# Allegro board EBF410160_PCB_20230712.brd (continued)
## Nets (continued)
CTP0_RST: J6.61 J21.12 R166.2
CTP1_INT: J7.55 J22.11 R164.2
CTP1_RST: J7.57 J22.12 R168.2
DBG_RX: R40.2 U10.2(A)
DBG_RXD: D6.2 J9.3 R40.1
DBG_TX: R39.2 U9.4(Y)
DBG_TXD: D5.2 J9.2 R39.1
DM4: D38.2 J27.36(USB-D-) R210.1
DP4: D39.2 J27.38(USB-D+) R211.1
DSI0_RST: J5.60 J21.15
DSI0_TE: J5.58 R160.1
DSI1_RST: J7.53 J22.15
DSI1_TE: J7.51 R161.1
EDP_AUXN: C146.2 J25.10 R191.2
EDP_AUXP: C147.2 J25.9 R188.2
EDP_BL_EN: J4.39 J25.22
EDP_BL_PWM: J5.5 J25.23
EDP_HPDIN_M0: J6.66 J25.17
EDP_PWR_EN: J6.76 R192.1 R196.1
EDP_TP_INT: J7.65 J26.2 R189.2
EDP_TP_RESET: J6.57 J26.3 R190.2
EDP_TX_AUXN: C146.1 J6.62
EDP_TX_AUXP: C147.1 J6.60
EDP_TX_D0N: J6.44 J25.6
EDP_TX_D0P: J6.42 J25.7
EDP_TX_D1N: J6.48 J25.3
EDP_TX_D1P: J6.46 J25.4
EXT_PWR_EN: J4.27 R1.1 R3.1 R19.1 R24.1
FAN: C30.1 Q1.2(SOURCE) R9.2 R10.2 R12.1
FSPI_CLK: J6.29 U8.6(CLK)
FSPI_CS0N: J6.31 U8.1(C\S\)
FSPI_D0: J6.33 J8.2 U8.5(DI/IO0)
FSPI_D1: J6.35 U8.2(DO/IO1)
FSPI_D2: J6.37 R36.2 U8.3(W\P\/IO2)
FSPI_D3: J6.39 R37.2 U8.7(HOLD/IO3)
GMAC1_INT: J5.10 R111.1
GMAC1_MCLKINOUT_M1: J7.56 R112.1 R113.1
GMAC1_MDC_M1: J7.62 R108.2 U16.13(MDC)
GMAC1_MDIO_M1: J7.60 R109.2 U16.14(MDIO)
GMAC1_RSTN: C84.1 D28.1 J5.4
GMAC1_RXCLK_M1: J7.36 R95.2 R101.1
GMAC1_RXD0_M1: J7.34 R93.2 R96.1
GMAC1_RXD1_M1: J7.32 R94.2 R97.1
GMAC1_RXD2_M1: J7.30 R99.1 R103.1
GMAC1_RXD3_M1: J7.28 R100.1 R104.1
GMAC1_RXDV_CRS_M1: J7.38 R102.1 R105.1
GMAC1_TXCLK_M1: J7.44 U16.20(TXC)
GMAC1_TXD0_M1: J7.52 U16.18(TXD0)
GMAC1_TXD1_M1: J7.50 U16.17(TXD1)
GMAC1_TXD2_M1: J7.48 U16.16(TXD2)
GMAC1_TXD3_M1: J7.46 U16.15(TXD3)
GMAC1_TXEN_M1: J7.42 U16.19(TXCTL)
GPIO2_B7: J7.47 R48.2
GPIO2_C0: J7.49 R49.2
HDMI_5V: C129.1 D32.1 D37.2 Q9.1(GATE) Q10.1(GATE) R157.1 R159.1 U25.18
HDMI_TX0N_PORT: J5.48 U25.9 U27.4(D2+) U27.7(NC3)
HDMI_TX0P_PORT: J5.46 U25.7 U27.5(D2-) U27.6(NC4)
HDMI_TX1N_PORT: J5.44 U25.6 U26.1(D1+) U26.10(NC1)
HDMI_TX1P_PORT: J5.42 U25.4 U26.2(D1-) U26.9(NC2)
HDMI_TX2N_PORT: J5.40 U25.3 U26.4(D2+) U26.7(NC3)
HDMI_TX2P_PORT: J5.38 U25.1 U26.5(D2-) U26.6(NC4)
HDMI_TX_CEC_PORT: D36.2 Q8.3(DRAIN) U25.13
HDMI_TX_HPD_PORT: D33.2 R153.2 R154.1 U25.19
HDMI_TX_HPDIN: J5.34 R153.1
HDMI_TXCLKN_PORT: J5.50 U25.12 U27.1(D1+) U27.10(NC1)
HDMI_TXCLKP_PORT: J5.52 U25.10 U27.2(D1-) U27.9(NC2)
HDMI_TXDDC_SCL_PORT: D35.2 Q9.3(DRAIN) R157.2 U25.15
HDMI_TXDDC_SDA_PORT: D34.2 Q10.3(DRAIN) R159.2 U25.16
HDMITX_CEC_M0: J5.32 Q8.2(SOURCE) R155.2
HDMITX_SCL: J5.30 Q9.2(SOURCE) R156.2
HDMITX_SDA: J5.28 Q10.2(SOURCE) R158.2
HOST1_DM: J18.2(D-) R136.1 U19.4(D2+) U19.7(NC3)
HOST1_DP: J18.3(D+) R137.1 U19.5(D2-) U19.6(NC4)
HP_DET: C173.1 J6.80 R215.1
HP_SNS: J4.36 J28.1 J29.1 R216.1 R218.1
HPL_OUT: C175.1 J4.34
HPR_OUT: C176.1 J4.38
HUB_3V3: C126.1 C127.1 C128.1 R144.1 R145.1 R151.2 U22.1(OVCUR#) U22.20(VDD3V3)
HUB_DM1: R129.2 U22.11(DM1)
HUB_DM2: R138.2 U22.9(DM2)
HUB_DM3: R131.2 U22.7(DM3)
HUB_DM4: R210.2 U22.5(DM4)
HUB_DP1: R130.2 U22.12(DP1)
HUB_DP2: R139.2 U22.10(DP2)
HUB_DP3: R132.2 U22.8(DP3)
HUB_DP4: R211.2 U22.6(DP4)
I2C0_SCL_PMIC: J6.3 U12.6(SCL)
I2C0_SDA_PMIC: J6.5 U12.5(SDA)
I2C1_SCL: J6.7 J21.9 J23.6 R163.2
I2C1_SDA: J6.9 J21.10 J23.5 R167.2
I2C2_SCL_M1: J6.51 R222.2
I2C2_SDA_M1: J6.53 R221.2
I2C3_SCL_M0: J6.72 R219.2
I2C3_SDA_M0: J6.70 R220.2
I2C4_SCL_M0: J7.29 J26.4
I2C4_SDA_M0: J7.31 J26.5
I2C5_SCL_M0: J7.25 J22.9 J24.6 R165.2
I2C5_SDA_M0: J7.27 J22.10 J24.5 R169.2
LCD0_BL_PWM: J5.9 J21.13
LCD1_BL_PWM: J5.11 J22.13
MDIN0_PHY: J17.3(TD1-) U16.2(MDIN0)
MDIN1_PHY: J17.7(RD1-) U16.5(MDIN1)
MDIN2_PHY: J17.6(TD2-) U16.7(MDIN2)
MDIN3_PHY: J17.9(RD2-) U16.10(MDIN3)
MDIP0_PHY: J17.2(TD1+) U16.1(MDIP0)
MDIP1_PHY: J17.4(RD1+) U16.4(MDIP1)
MDIP2_PHY: J17.5(TD2+) U16.6(MDIP2)
MDIP3_PHY: J17.8(RD2+) U16.9(MDIP3)
MIC_INN: C174.2 D44.2 J4.30 J30.1 R217.1
MIC_INP: C174.1 D41.2 J4.28 J29.2 J29.3 J29.4 J29.5 J30.2 R213.2
MINIPCIE_3V3: C155.1 C159.1 C160.1 C161.1 C167.1 C168.1 C169.1 C170.1 J27.2(VBAT1) J27.24(VBAT5) J27.39(VBAT2) J27.41(VBAT3) J27.52(VBAT4) L10.2 R201.1 R205.1
MINIPCIE_NWDISABLE: J7.61 R208.2
MIPI0_PWR_EN: J6.74 R171.1
MIPI1_PWR_EN: J5.16 R170.1
MIPI_CSI_RX_CLK0N: J5.78 J23.10
MIPI_CSI_RX_CLK0P: J5.76 J23.9
MIPI_CSI_RX_CLK1N: J5.77 J24.10
MIPI_CSI_RX_CLK1P: J5.75 J24.9
MIPI_CSI_RX_D0N: J5.70 J23.12
MIPI_CSI_RX_D0P: J5.68 J23.11
MIPI_CSI_RX_D1N: J5.74 J23.8
MIPI_CSI_RX_D1P: J5.72 J23.7
MIPI_CSI_RX_D2N: J5.69 R178.1 R180.1
MIPI_CSI_RX_D2P: J5.67 R176.1 R177.1
MIPI_CSI_RX_D3N: J5.73 R184.1 R185.1
MIPI_CSI_RX_D3P: J5.71 R182.1 R183.1
MIPI_DSI_TX0_CLKN: J5.53 J21.24
MIPI_DSI_TX0_CLKP: J5.51 J21.23
MIPI_DSI_TX0_D0N: J5.43 J21.27
MIPI_DSI_TX0_D0P: J5.41 J21.26
MIPI_DSI_TX0_D1N: J5.47 J21.21
MIPI_DSI_TX0_D1P: J5.45 J21.20
MIPI_DSI_TX0_D2N: J5.59 J21.18
MIPI_DSI_TX0_D2P: J5.57 J21.17
MIPI_DSI_TX0_D3N: J5.63 J21.30
MIPI_DSI_TX0_D3P: J5.61 J21.29
MIPI_DSI_TX1_CLKN: J5.27 J22.24
MIPI_DSI_TX1_CLKP: J5.25 J22.23
MIPI_DSI_TX1_D0N: J5.17 J22.27
MIPI_DSI_TX1_D0P: J5.15 J22.26
MIPI_DSI_TX1_D1N: J5.21 J22.21
MIPI_DSI_TX1_D1P: J5.19 J22.20
MIPI_DSI_TX1_D2N: J5.33 J22.18
MIPI_DSI_TX1_D2P: J5.31 J22.17
MIPI_DSI_TX1_D3N: J5.37 J22.30
MIPI_DSI_TX1_D3P: J5.35 J22.29
OTG0_DM: D30.2 J19.A7(DN1) J19.B7(DN2) R133.1
OTG0_DP: D31.2 J19.A6(DP1) J19.B6(DP2) R134.1
PCIE20_CLKREQN_M0: J7.37 R207.1
PCIE20_PERSTN_M0: J7.59 R209.2
PCIE20_REFCLKN: J4.54 J27.11(VDD-EXT)
PCIE20_REFCLKP: J4.52 J27.13(RESERVED)
PCIE20_RXN: J4.48 J27.23(UART-RXD)
PCIE20_RXP: J4.46 J27.25(UART-RTS)
PCIE20_TXN: C165.1 J4.44
PCIE20_TXP: C166.1 J4.42
PCIE20_WAKEN_M0: J7.39 R206.1
PCIE_PWR_EN: J4.43 R204.1
PE_TXN: C165.2 J27.31(UART-TXD)
PE_TXP: C166.2 J27.33(PERST2)
PHY1_LED1: J17.14(YELA) R116.1 U16.33(LED1)
PHY1_LED2: J17.11(GRLA) R117.1 U16.34(LED2)
PHY_CLKOUT125: R112.2 U16.35(CLKOUT)
PWM2_M0: J5.8 R17.1
PWM3_IR: C62.1 J5.7 R46.1
PWR_3V3_EN: J6.59 R30.1
PWR_5V_EN: J4.35 R32.1
PWR_12V_EN: J4.41 R28.1
PWRON_KEY: C56.1 D3.2 J4.25 SW1.3(B1) SW1.4(B2)
RECOVERY: J6.16 R41.2
RESET_KEY: C58.1 D4.2 J4.29 SW2.3(B1) SW2.4(B2)
RS485_1_A: D26.2 J13.1 R71.2 R80.1 U14.6(A)
RS485_1_B: D24.2 R73.1 R76.1 R79.1 U14.7(B)
RS485_2_A: D27.2 J14.1 R72.2 R82.1 U15.6(A)
RS485_2_B: D25.2 R74.1 R78.1 R81.1 U15.7(B)
RX8010_NIRQ1: J5.64 U12.7(/IRQ1)
RX8010_NIRQ2: J5.62 U12.3(/IRQ2)
RXD1_232: D12.2 R58.1 U13.13(R1IN)
RXD2_232: D11.2 R56.1 U13.8(R2IN)
SARADC_VIN1: J6.18 R43.2
SDMMC0_CLK: J6.13 R63.1
SDMMC0_CMD: J6.15 R62.1
SDMMC0_D0: J6.19 R64.1
SDMMC0_D1: J6.21 R65.1
SDMMC0_D2: J6.23 R60.1
SDMMC0_D3: J6.25 R61.1
SDMMC0_DET: J6.17 R66.1
SIM_CLK0: J27.12(USIM-CLK) R200.1
SIM_DATA0: J27.10(USIM-DATA) R202.1
SIM_RST0: J27.14(USIM-RST) R199.1
SIM_VDD: J27.8(USIM-VDD) R198.1 U36.1(VCC) U37.1
SPKN_OUT: D46.2 J4.24 J31.2
SPKP_OUT: D45.2 J4.22 J31.1
SS_TXN: C112.1 J18.8(TX-) U19.2(D1-) U19.9(NC2)
SS_TXP: C113.1 J18.9(TX+) U19.1(D1+) U19.10(NC1)
TXD1_232: D14.2 R59.1 U13.14(T1OUT)
TXD2_232: D13.2 R57.1 U13.7(T2OUT)
UART1_DIR: J7.43 R75.1 U14.2(R\E\) U14.3(DE)
UART1_RX_M0: J7.10 R69.2 U14.1(RXD)
UART1_TX_M0: J7.8 R67.2 U14.4(TXD)
UART2_RX_M0_DEBUG: J5.22 R42.2 U10.4(Y)
UART2_TX_M0_DEBUG: J5.20 R38.2 U9.2(A)
UART3_RX_M1: J7.5 R52.2 U13.9(R2OUT)
UART3_TX_M1: J7.3 R53.2 U13.10(T2IN)
UART4_RX_M1: J7.9 R54.2 U13.12(R1OUT)
UART4_TX_M1: J7.7 R55.2 U13.11(T1IN)
UART6_DIR: J7.45 R77.1 U15.2(R\E\) U15.3(DE)
UART6_RX_M0: J7.13 R70.2 U15.1(RXD)
UART6_TX_M0: J7.11 R68.2 U15.4(TXD)
UART7_RX_M0: J7.17 R223.2
UART7_TX_M0: J7.15 R224.2
UART9_RX_M1: J7.21 R225.2
UART9_TX_M1: J7.19 R226.2
USB2_HOST2_DM: J7.74 R126.1
USB2_HOST2_DP: J7.72 R125.1
USB2_HOST3_DM: J7.68 R142.2
USB2_HOST3_DP: J7.66 R141.2
USB3_HOST1_DM: J4.80 R136.2
USB3_HOST1_DP: J4.78 R137.2
USB3_HOST1_SSRXN: J4.60 J18.5(RX-) U18.2(D1-) U18.9(NC2)
USB3_HOST1_SSRXP: J4.58 J18.6(RX+) U18.1(D1+) U18.10(NC1)
USB3_HOST1_SSTXN: C112.2 J4.64
USB3_HOST1_SSTXP: C113.2 J4.62
USB20_HOST_PWR_EN: J7.67 R140.1
USB20_OTG_PWR_EN: J4.37 R149.1
USB30_HOST_PWR_EN: J5.14 R146.1
USB OTG: C123.1 C124.1 J19.A4(VBUS1) J19.A9(VBUS2) J19.B4(VBUS4) J19.B9(VBUS3) R148.1 U24.1(OUT)
USB_OTG0_DM: J6.6 R133.2
USB_OTG0_DP: J6.4 R134.2
USB_OTG0_ID: J6.10 R135.2
USB_OTG0_VBUSDET: J6.12 R148.2 R150.1
USER_LED: J5.6 R45.2
WLAN_PWR_EN: J4.45 R128.1
N02088: F1.1 J1.4
N03633: C7.1 U3.6(BOOT)
N03641: C7.2 L1.1 U3.2(SW)
N03801: C8.2 R4.2 R6.1 U3.4(FB)
N28501: C28.1 U5.6(BOOT)
N28533: C28.2 L3.1 U5.2(SW)
N15118698: C4.1 R1.2 U1.4(EN)
N15119063: R2.1 U1.3(ISET)
N15122947: C9.1 R3.2 U2.4(EN)
N15123057: R5.1 U2.3(ISET)
N15599533: R96.2 U16.25(RXD0)
N15599537: R97.2 U16.24(RXD1)
N15599541: R99.2 U16.23(RXD2)
N15599545: R100.2 U16.22(RXD3)
N15599549: R101.2 U16.27(RXC)
N15599553: R102.2 U16.26(RXCTL)
N15599792: R90.2 R91.1 R93.1 R94.1 R95.1
N15600759: R106.2 R107.1 R108.1 R109.1
N15600826: R110.2 R111.2 U16.31(INTB)
N15601838: C81.1 U16.37(XTAL_OUT) Y1.1
N15601846: C82.1 U16.36(XTAL_IN) Y1.3
N15602173: D28.2 R119.2 R120.2 U16.12(PHYRSTB)
N15602572: R118.1 U16.32(LED0)
N15602600: R117.2 R121.2 R122.1
N15603170: C83.1 J17.1(CT)
N15605512: R98.1 U16.39(RSET)
N15605755: C77.1 C78.1 R89.1 R92.1 U16.28(DVDD_RG)
N15611443: C116.1 R140.2 U21.4(EN)
N15611553: R143.1 U21.3(ISET)
N15653247: C122.1 R149.2 U24.4(EN)
N15653357: R152.1 U24.3(ISET)
N15653957: C119.1 R146.2 U23.4(EN)
N15654067: R147.1 U23.3(ISET)
N15659726: C18.2 R7.2 R8.1 U3.5(EN)
N15752445: L9.1 U25.G1(20) U25.G2(21) U25.G3(22) U25.G4(23)
N15772454: J22.14 R161.2
N15774097: J21.14 R160.2
N15830872: C176.2 D43.2 J28.3 J28.5
N15830941: C175.2 D42.2 J28.2 R215.2
N15838979: J28.4 R214.2
N15851038: C171.1 R212.2 R213.1
N15980269: J13.2 R73.2
N16735828: LED2.1(CATHODE) R45.1
N16735933: LED3.1(CATHODE) R48.1
N16793147: D15.2 J12.1(DAT2) R60.2
N16793149: D19.2 J12.7(DAT0) R64.2
N16793151: D18.2 J12.5(CLK) R63.2
N16793153: D17.2 J12.3(CMD) R62.2
N16793155: D16.2 J12.2(CD/DAT3) R61.2
N16793157: D20.2 J12.8(DAT1) R65.2
N16793300: D21.2 J12.9(CD) R66.2
N16795570: LED4.1(CATHODE) R49.1
N16795883: C37.2 R23.2 R24.2 R25.1 U5.5(EN)
N16811933: J27.1(MIC-P) R205.2 R206.2
N16823854: J27.7(SPK-N) R207.2
N16928945: J27.20(W-DISABLE) R208.1
N16929135: J27.22(PERST1) R209.1
N16980859: C164.1 R199.2 U36.2(RST) U37.6
N16980861: C163.1 R200.2 U36.3(CLK) U37.4
N16980863: C162.1 R198.2 R202.2 U36.7(I/O) U37.5
N17405290: C29.2 R20.2 R22.1 U5.4(FB)
N17423559: C19.1 U4.6(BOOT)
N17423580: C19.2 L2.1 U4.2(SW)
N17423608: C27.2 R14.2 R15.1 U4.5(EN)
N17423737: C20.2 R11.2 R13.1 U4.4(FB)
N17430242: R33.1 U7.3(ISET)
N17430314: C44.1 R32.2 U7.4(EN)
N17443353: R31.1 U6.3(ISET)
N17443371: C41.1 R30.2 U6.4(EN)
N17444423: C38.2 Q5.1(GATE) Q6.3(COLLECTOR) R27.2
N17444523: Q6.1(BASE) R28.2 R29.1
N17454508: C69.2 U13.1(C1+)
N17454513: C69.1 U13.3(C1-)
N17455367: C70.2 U13.4(C2+)
N17455372: C70.1 U13.5(C2-)
N17455499: C68.1 U13.6(V-)
N17455508: C66.1 U13.2(V+)
N17466585: L4.1 U16.30(REG_OUT)
N17592125: C154.1 U35.6(BOOT)
N17592129: C154.2 L10.1 U35.2(SW)
N17592172: C155.2 R201.2 R203.1 U35.4(FB)
N17592220: R204.2 U35.5(EN)
N17633217: C117.1 U22.3(XOUT) Y2.1
N17633237: C118.2 U22.4(XIN) Y2.3
N17633305: R144.2 U22.16(RESET#/CDP)
N17633317: R145.2 U22.18(PSELF)
N17685591: C151.2 Q12.1(GATE) Q13.3(COLLECTOR) R195.2
N17685601: Q13.1(BASE) R196.2 R197.1
N17685851: Q12.2(SOURCE) R193.2
N17690217: R194.1 U34.3(ISET)
N17690290: C148.1 R192.2 U34.4(EN)
N17695706: C133.1 R171.2 U28.4(EN) U30.4(EN)
N17695791: R174.1 U30.3(ISET)
N17695827: R173.1 U28.3(ISET)
N17697466: J17.13(YELC) R114.1
N17697880: R181.1 U32.3(ISET)
N17697953: C140.1 R179.2 U32.4(EN)
N17701231: J14.2 R74.2
N17702194: J15.3 R81.2
N17702199: J15.4 R82.2
N17702222: J15.2 R80.2
N17702231: J15.1 R79.2
N17728858: D22.1 R71.1
N17729021: D23.1 R72.1
N17731599: J11.6 R59.2
N17731608: J11.4 R58.2
N17731627: J11.1 R56.2
N17748815: Q5.2(SOURCE) R26.2
N17750545: Q1.1(GATE) Q2.3(COLLECTOR) R12.2
N17750554: D2.1(K) J2.1 Q1.3(DRAIN)
N17750632: Q2.1(BASE) R17.2 R18.1
N17759502: C65.1 D9.3 U12.8(VDD)
N17770939: R141.1 U22.15(DPU)
N17770942: R142.1 U22.14(DMU)
N17861933: C63.1 C64.1 R47.1 U11.2(VCC)
N17863087: R44.2 R46.2 U11.3(OUT)
N17946485: C60.1 D7.2 R41.1 SW3.3(B1) SW3.4(B2)
N17975561: D10.2 J10.1 R50.2 R51.1
N18056005: C107.2 Q7.1(GATE) R127.2 R128.2
N18056634: C104.1 C105.1 U17.2(RF0)
N18056637: C104.2 C106.1 CN1.1
N18057325: R126.2 U17.7(D-)
N18057335: R125.2 U17.6(D+)
N18091011: D9.1 R50.1
N18111918: C130.1 R170.2 U29.4(EN) U31.4(EN)
N18111989: R175.1 U31.3(ISET)
N18112037: R172.1 U29.3(ISET)
N18115454: R187.1 U33.3(ISET)
N18115527: C143.1 R186.2 U33.4(EN)
N18173560: J19.C1(SH1) J19.C2(SH2) J19.C3(SH3) J19.C4(SH4) L8.1
N18175084: D29.3 R135.1
N18245213: LED1.1(CATHODE) Q3.3(COLLECTOR)
N18245628: LED1.2(ANODE) R16.2
N18246356: Q3.1(BASE) R19.2 R21.1
N18288623: C61.1 D8.2 R43.1 R227.1 SW4.3(B1) SW4.4(B2)
N18353176: J17.12(GRLC) R115.1
N18355550: J11.3 R57.2
N18579208: D48.2 J33.2 R219.1
N18579211: D47.2 J33.3 R220.1
N18585387: D50.2 J32.2 R222.1
N18585389: D49.2 J32.3 R221.1
N18585721: D52.2 J34.2 R224.1
N18585723: D51.2 J34.3 R223.1
N18585912: D54.2 J35.2 R226.1
N18585914: D53.2 J35.3 R225.1

Pads without a net: J4 33 47 51 53 55 57 59 61 63 65 68 69 70 71 72 74 75 77 79; J6 22 24 26 28 32 34 36 38 43 45 47 49 50 52 54 56 63 67 71 73 77; J7 4 6 14 16 18 20 22 24; J9 1; J18 14 15 17 18; J19 A8 B8; J23 13 14; J24 13 14 16 17 18 19 20 21; J25 1 14 24 25 30; J27 3 5 6 16 17 19 28 30 32 42 44 45 46 47 48 49 51; NOREF#8 1; NOREF#31 1; NOREF#35 1; NOREF#43 1; NOREF#46 1; NOREF#47 1; NOREF#48 1; NOREF#49 1; U12 1 2; U17 3 4 9 10 11 12 13 14; U22 2 13 17 19 21 22 23 24; U25 14; U36 4 6; U37 3

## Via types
v1: diameter 0.508, hole 0.305, TOP to BOTTOM, 1177 vias

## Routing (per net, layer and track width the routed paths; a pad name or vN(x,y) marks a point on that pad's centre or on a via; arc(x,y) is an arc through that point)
1V05_AVDD_PHY: length 3.2
  TOP w0.203: v1(81.27,62.98) 81.27,62.89 U16.3 ; v1(84.71,63.27) 84.71,63.01 U16.38 ; v1(79.76,61.47) 79.87,61.47 U16.8
1V05_DVDD_PHY: length 0.5
  TOP w0.254: U16.21 v1(83.06,56.41)
1V05_PHY:
  vias: v1(86.87,54.86) v1(86.87,53.85)
1V8_DVDD_PHY: length 37.6
  TOP w0.254: v1(78.99,49.27) R106.1 78.99,50.04 71.88,50.04 70.87,51.05 v1(70.87,57.28)
  TOP w0.381: R90.1 v1(88.14,51.81) ; L7.1 92.54,50.05 C101.1 C102.1
  BOTTOM w0.254: v1(70.87,57.28) 70.87,61.75 70.61,62 69.49,62 69.47,61.98 R119.1 ; v1(88.14,51.81) 88.14,49.27 86.87,48 80.26,48 v1(78.99,49.27)
  vias: v1(89.15,51.81)
3V3_AVDD_PHY: length 2.8
  TOP w0.203: v1(78.99,59.94) 79.27,59.94 U16.11
  TOP w0.254: v1(83.31,64.26) 83.69,63.88 83.69,63.12 U16.40
3V3_DVDD_PHY: length 58.2
  TOP w0.203: U16.29 86.18,58.55 v1(86.49,58.55)
  TOP w0.254: v1(69.85,57.28) 69.85,50.29 71.4,48.74 79.48,48.74 v1(80.01,49.27) R107.2 ; R118.2 R110.1 v1(91.57,56.13)
  TOP w0.381: v1(89.79,53.85) 89.8,53.86 C86.1 C85.1 92.54,53.86 L5.1 ; R91.2 v1(87.12,51.81) 88.27,52.96 v1(89.79,52.96)
  TOP w0.508: v1(89.79,53.85) v1(89.79,52.96)
  BOTTOM w0.254: v1(80.01,49.27) 80.64,48.64 86.21,48.64 87.12,49.55 v1(87.12,51.81) ; R120.1 68.33,61.23 69.85,59.71 v1(69.85,57.28)
  BOTTOM w0.381: C87.1 86.11,58.93 v1(86.49,58.55) 88.01,58.55 88.14,58.67 ; 88.14,58.67 88.39,58.42 90.42,58.42 91.57,57.28 v1(91.57,56.13) 91.57,54.74 90.68,53.85 v1(89.79,53.85) ; 88.14,58.67 R122.2
  BOTTOM w0.508: R92.2 89.04,53.85 v1(89.79,53.85)
3V3_EDP: length 43.5
  TOP w0.254: R188.1 v1(125.18,23.37) ; C150.1 v1(127.55,26.03)
  BOTTOM w0.254: R190.1 R189.1 57.91,20.32 57.15,19.56 v1(57.15,16.13)
  BOTTOM w0.508: v1(125.18,23.37) 126.36,23.37 127.55,24.55 v1(127.55,26.03) 127.13,26.45 127.13,31.49 128.02,32.38 128.02,34.92 127.25,35.69 121.03,35.69 119.85,36.87 C149.1 118.72,37.02 U34.1 ; v1(57.15,16.13) 57.15,11.05 57.54,10.65 J26.1
3V3_IMAGE_1: length 3.6
  TOP w0.254: 125.73,65.78 v1(125.73,66.8)
  BOTTOM w0.254: v1(125.73,66.8) 125.73,68.32 R162.1 R166.1
3V3_IMAGE_2: length 5.4
  TOP w0.254: U31.1 124.14,46.92 124.84,47.62 R164.1 R168.1
3V3_OUT: length 9.3
  BOTTOM w0.508: J3.5 4.06,34.14 4.06,33.39 C43.1 7.07,31.49 C42.1 8.15,31.79 8.6,32.24 U6.1
3V3_WLAN: length 10.2
  TOP w0.381: U17.8 95.16,36.64 95.1,36.7 C109.1 94.48,37.67 C108.1 94.78,38.69 94.48,38.99 91.61,38.99 91.34,38.72 Q7.3
5V_OUT: length 8.8
  BOTTOM w0.508: U7.1 7.82,36.81 C45.1 7.37,36.23 7.19,36.06 C46.1 5.97,36.23 J3.3
12V_OUT: length 8.4
  BOTTOM w0.635: Q5.3 7.91,40.26 C39.1 6.27,40.8 C40.1 5.7,40.5 J3.1
GND: length 1722.7
  TOP w0.156: J6.68 v1(65.63,26.1) ; J7.33 57.13,59.59 v1(56.63,59.09)
  TOP w0.203: J7.71 v1(66.63,60.11) ; J7.54 v1(62.13,56.11) ; J5.80 v1(43.63,56.13) ; J7.76 v1(67.63,59.13) ; J22.25 131.88,54.03 v1(131.95,54.1) ; J7.58 63.13,56.33 63.12,56.32 63.12,55.6 v1(63.63,55.09) ; J5.54 37.13,56.47 37.22,56.38 37.22,54.74 v1(36.58,54.1) ; J22.28 131.51,55.53 131.6,55.44 132.91,55.44 v1(133.35,55.88) ; J7.12 v1(51.63,56.13) ; J7.2 v1(49.13,56.13) ; J4.31 v1(31.63,19.05) ; J7.23 v1(54.63,60.12) ; J7.79 v1(68.63,60.11) ; J22.22 131.52,52.53 v1(131.95,52.96) ; J7.26 v1(55.13,56.11) ; J5.66 v1(40.13,56.13) ; J4.49 v1(36.13,19.05) ; J7.40 v1(58.63,56.11) ; J4.67 v1(40.63,22.1) ; J4.73 v1(42.13,22.1)
  TOP w0.254: J7.64 v1(64.63,56.11) ; J5.49 v1(36.13,63.18) ; J4.40 33.63,26.14 ; 33.63,26.14 v1(33.64,26.14) ; 33.63,26.14 33.63,46.46 v1(34.67,47.5) ; v1(31.88,64.13) 31.46,64.13 31.02,63.69 31.02,63.03 31.13,62.91 J5.29 ; J6.2 v1(49.13,26.11) ; 102.61,59.94 101.82,59.94 101.56,59.68 v1(101.56,56.13) C118.1 ; 102.61,59.94 v1(102.62,59.94) 105.7,59.94 105.96,59.69 v1(105.96,56.13) C117.2 104.91,56.5 Y2.4 ; 102.61,59.94 Y2.2 ; D54.1 v1(110.36,19.43) ; J6.64 v1(64.63,26.1) ; J4.23 29.63,19.28 v1(29.36,19.01) ; SW4.2 v1(2.07,52.58) ; v1(39.62,60.07) 39.88,60.07 40.13,60.32 J5.65 ; SW2.2 2.08,71.56 1.42,71.56 1.27,71.71 v1(0.76,71.71) ; J6.58 v1(63.13,26.1) ; J5.79 43.63,64.32 v1(43.18,64.77) ; J21.16 131.03,71.62 131.21,71.8 131.21,72.87 130.96,73.12 J21.19 v1(128.91,73.12) ; v1(84.7,70.1) 87.5,70.1 88.14,69.47 88.14,67.44 ; v1(84.7,70.1) 84.07,70.1 83.57,69.59 83.57,68.93 ; v1(84.7,70.1) Y1.4 83.58,68.95 83.57,68.93 ; J6.30 v1(56.13,26.1) ; J4.67 40.63,18.81 ; R105.2 v1(85.09,49.27) ; C58.2 v1(1.91,65.02) ; D8.1 C61.2 v1(1.4,46.99) ; C177.2 v1(44.83,72.13) ; J6.55 62.63,21.7 v1(62.23,22.1) ; v1(66.15,59.09) 66.13,59.08 J7.70 ; J7.23 54.63,62.99 ; J6.69 66.13,22.03 v1(66.06,22.1) ; J27.54 118.85,72.16 v1(118.36,72.64) ; D41.1 v1(47,68.46) ; 88.14,67.44 88.14,67.07 87.48,66.42 v1(87.37,66.42) ; 88.14,67.44 88.13,67.45 Y1.2 87,66.79 v1(87.37,66.42) ; J6.41 v1(59.13,19.18) ; v1(27.13,54.12) 28.13,55.12 J5.18 ; v1(128.4,49.78) 128.65,49.53 J22.16 ; v1(128.91,77.62) J21.28 130.96,77.62 131.05,77.71 132.96,77.71 v1(133.57,77.1) ; v1(87.37,66.42) C82.2 ; R191.1 v1(125.18,24.89) ; R21.2 11.8,40.34 Q3.2 12.36,40.89 v1(14.48,40.89) ; J7.33 57.13,63.09 ; J4.73 42.13,18.96 ; J5.23 v1(29.63,63.24) ; J4.50 v1(36.13,23.11) ; v1(2.79,73.4) 2.68,73.52 C56.2 D3.1 2.08,75.65 SW1.1 v1(2.08,77.33) ; J21.22 v1(128.91,74.62) ; v1(31.63,23.11) J4.32 31.62,24.63 v1(31.62,30.99) v1(31.62,32) 31.62,32 v1(31.62,39.62) v1(31.62,40.89) 31.62,48.48 32.26,49.12 44.24,49.12 46.61,51.49 46.61,61.29 49.4,64.09 v1(49.4,64.13) 49.4,64.4 R217.2 ; J4.26 v1(30.13,26.16) v1(30.13,32) v1(30.13,34.54) v1(30.13,39.62) v1(30.13,40.89) v1(30.13,48.51) 30.13,49.05 31.53,50.45 43.69,50.45 45.25,52.01 45.25,62.14 v1(47.24,64.13) ; J6.40 v1(58.63,26.1) ; R103.2 v1(82.04,49.27) ; D47.1 v1(97.28,19.43) ; v1(27.3,23.11) 27.63,23.44 J4.16 ; J6.1 v1(49.13,19.18) ; R113.2 v1(95.12,58.58) ; J25.11 v1(131.06,24.93) ; J6.11 51.63,19.43 51.88,19.18 v1(52.15,19.18) ; J21.25 v1(128.91,76.12) ; v1(32.89,64.13) 33.63,63.4 J5.39 33.63,60.6 34.16,60.07 v1(34.16,60.07) ; J25.5 v1(131.06,21.93) ; SW3.1 0.94,58.34 v1(0.76,58.16) ; U8.4 v1(81.15,28.7) ; J25.15 130.84,26.93 v1(131.06,27.15) ; D51.1 v1(100.33,19.43) ; D39.1 v1(96.74,57.67) ; D7.1 v1(1.99,56.89) ; v1(28.96,23.11) 28.63,23.44 J4.20 28.63,40.84 v1(28.57,40.89) 28.57,47.12 v1(27.18,48.51) ; J5.2 v1(24.13,56.24) ; J4.66 v1(40.13,23.11) ; D53.1 v1(111.38,19.43) ; D4.1 v1(1.91,66.04) ; SW1.2 v1(2.08,81.53) ; D44.1 v1(50.03,68.45) ; R98.2 82.3,66.67 v1(82.04,66.93) ; v1(55.63,22.1) J6.27 55.63,19.05 ; D38.1 v1(100.25,57.67) ; v1(68.07,22.1) 67.63,21.65 J6.75 ; SW4.1 v1(2.07,50.29) ; J22.6 130.89,44.53 v1(131.19,44.83) ; J25.8 v1(131.06,23.43) ; J6.8 50.63,26.97 v1(50.16,27.43) ; J4.56 v1(37.63,23.11) ; J25.2 v1(131.06,20.43) ; v1(75.39,65.15) 75.39,66.34 70.06,71.67 J17.10 ; v1(27.13,63.24) J5.13 v1(27.13,60.24) ; 83.57,68.93 83.57,67.04 84.18,66.42 v1(84.21,66.42) C81.2 ; J22.7 v1(128.84,45.03) ; v1(128.78,51.94) 128.78,51.43 129.19,51.03 J22.19 ; SW3.2 v1(0.76,62.54) ; J6.79 68.63,21.64 v1(69.09,22.1) ; C171.2 v1(45.85,68.45) ; J5.55 37.63,62.77 38.1,63.24 v1(38.1,64.01) ; C150.2 v1(125.18,26.03) ; J5.36 v1(32.63,56.13) ; D48.1 v1(96.27,19.43) ; SW2.1 v1(2.08,68.45) ; J5.3 v1(24.63,63.24) ; C60.2 v1(1.99,55.88) ; C172.2 v1(43.13,66.68) ; D52.1 v1(99.31,19.43) ; J6.14 v1(52.13,26.1) ; J4.76 v1(42.63,23.11) ; R104.2 v1(81.03,49.27)
  TOP w0.381: J27.4 114.8,61.98 v1(115.19,61.59) ; v1(95.76,69.85) 96,70.09 J27.43 ; J27.29 v1(101.6,69.82) ; C65.2 v1(17.28,65.66) ; J27.26 v1(102.8,64.51) ; C88.2 v1(94.79,53.86) ; v1(99.19,64.51) 99.6,64.1 J27.34 ; v1(19.68,66.8) 20.07,66.42 R18.2 20.58,66.5 20.99,66.92 Q2.2 ; C101.2 v1(91.57,51.81) ; v1(112.8,72.65) J27.9 ; J27.35 v1(99.2,69.82) ; v1(97.2,64.51) J27.40 ; C108.2 93.48,37.67 C109.2 v1(92.67,36.7) ; J27.21 v1(104.8,69.82) ; J27.50 v1(93.2,61.47) ; U17.5 v1(96.27,27.81) ; v1(110.4,69.44) J27.15 ; C102.2 v1(90.55,51.81) ; U11.1 v1(122.94,10.29) ; v1(106.17,64.51) 106,64.34 J27.18 ; J27.37 v1(98.4,72.65) ; U11.4 v1(126.75,10.29) ; J27.27 v1(102.4,72.65) ; C30.2 v1(28.19,66.42)
  TOP w0.508: C54.2 C55.2 85.94,26.53 v1(85.81,26.67) v1(84.71,26.67) ; J10.2 18.13,72.11 D10.1 v1(18.77,72.01) ; J17.10 67.75,74.74 67.18,74.17 v1(67.18,72.01) ; R197.2 v1(120.9,28.36) ; D2.2 v1(21.92,72.77)
  TOP w0.635: J11.2 27.71,17.2 ; J11.2 26.64,16.12 ; J11.2 28.79,16.12 ; J11.2 27.71,15.04 ; 18.5,79.19 J1.3 ; J1.3 18.5,82.14 ; J1.3 17.77,80.66 ; J1.3 19.23,80.66 ; J11.5 17.36,16.12 ; J11.5 15.21,16.12 ; J11.5 16.28,17.2 ; J11.5 16.28,15.04 ; 108.15,78.49 J20.10 ; J20.10 109.15,77.49 ; J20.10 109.15,79.49 ; J20.10 110.15,78.49 ; J21.31 133.86,80.77 ; J21.31 132.68,79.8 ; J21.31 132.68,81.75 ; J21.31 131.51,80.77 ; J1.5 20.03,87.92 ; J1.5 18.67,87.92 ; J1.5 19.35,86.54 ; J20.5 106.1,77.32 ; J20.5 106.1,73.66 ; J20.5 107.93,75.49 ; J20.5 104.27,75.49 ; 1.78,41.69 J3.2 ; J3.2 3.24,41.69 ; J3.2 2.51,40.97 ; J3.2 2.51,42.42 ; 104.27,81.29 J20.11 ; J20.11 106.1,83.12 ; J20.11 107.93,81.29 ; J20.11 106.1,79.46 ; J34.4 106,11.38 ; J34.4 106,9.93 ; J34.4 106.73,10.65 ; J34.4 105.27,10.65 ; 118.85,69.19 J27.54 ; J27.54 120.1,70.67 ; J27.54 117.6,70.67 ; J20.12 119.2,83.12 ; J20.12 117.37,81.29 ; J20.12 121.03,81.29 ; J20.12 119.2,79.46 ; 2.15,27.47 J9.4 ; J9.4 3.05,28.37 ; J9.4 3.05,26.57 ; J9.4 3.95,27.47 ; J1.2 13.2,82.14 ; J1.2 13.93,80.66 ; J1.2 13.2,79.19 ; J1.2 12.47,80.66 ; J20.4 110.15,75.49 ; J20.4 109.15,74.49 ; J20.4 108.15,75.49 ; J20.4 109.15,76.49 ; 1.78,33.69 J3.6 ; J3.6 3.24,33.69 ; J3.6 2.51,34.42 ; J3.6 2.51,32.97 ; 131.51,58.67 J22.31 ; J22.31 132.68,57.7 ; J22.31 133.86,58.67 ; J22.31 132.68,59.65 ; J25.32 132.68,18.75 ; J25.32 133.86,17.78 ; J25.32 132.68,16.8 ; J25.32 131.51,17.78 ; 22.62,74.34 J2.2 ; J2.2 21.92,75.04 ; J2.2 22.62,75.74 ; 89.55,69.19 J27.53 ; J27.53 90.8,70.67 ; J27.53 88.3,70.67 ; J27.53 89.55,72.15 ; 18.13,75.33 J10.2 18.75,74.7 ; 82,9.93 J32.4 ; J32.4 82,11.38 ; J32.4 82.73,10.65 ; J32.4 81.27,10.65 ; J35.4 118,11.38 ; J35.4 117.27,10.65 ; J35.4 118.73,10.65 ; J35.4 118,9.93 ; J1.1 10.23,87.92 ; J1.1 8.87,87.92 ; J1.1 9.55,86.54 ; J18.22 100.2,84.15 ; J18.22 101.98,82.37 ; J18.22 98.42,82.37 ; J18.22 100.2,80.59 ; J33.4 94.73,10.65 ; J33.4 94,9.93 ; J33.4 94,11.38 ; J33.4 93.27,10.65 ; 87.06,74.91 J18.20 ; J18.20 85.28,76.69 ; J18.20 87.06,78.47 ; 1.78,37.69 J3.4 ; J3.4 3.24,37.69 ; J3.4 2.51,38.42 ; J3.4 2.51,36.97 ; J26.6 70,11.38 ; J26.6 70,9.93 ; J26.6 70.73,10.65 ; J25.31 132.68,37.55 ; J25.31 132.68,35.6 ; J25.31 131.51,36.58 ; J17.15 84.9,78.04 ; 100.2,74.91 J18.21 ; J18.21 101.98,76.69 ; J18.21 100.2,78.47 ; J21.32 133.86,61.97 ; J21.32 132.68,62.95 ; J21.32 131.51,61.97 ; J21.32 132.68,61 ; 119.2,77.32 J20.6 119.2,73.66 ; J22.32 132.68,40.85 ; J22.32 133.86,39.87 ; J22.32 131.51,39.87 ; J22.32 132.68,38.9 ; 66.63,78.04 J17.16 ; J18.19 87.06,84.15 ; J18.19 87.06,80.59 ; J18.19 85.28,82.37 ; J18.19 88.84,82.37
  GND02 w0.381: 22.62,74.34 J2.2 ; J2.2 22.62,75.74 ; J2.2 23.32,75.04 ; J2.2 21.92,75.04 ; J34.4 106.73,10.65 ; J34.4 106,9.93 ; J34.4 106,11.38 ; J34.4 105.27,10.65 ; J32.4 82.73,10.65 ; J32.4 81.27,10.65 ; J32.4 82,9.93 ; J32.4 82,11.38 ; SS6.1 116.3,21.9 ; SS6.1 113.52,19.12 ; SS6.1 116.3,16.34 ; SS6.1 119.08,19.12 ; J20.12 121.03,81.29 ; J20.12 119.2,79.46 ; J20.12 117.37,81.29 ; J20.12 119.2,83.12 ; J18.13 90.13,77.9 ; J18.13 90.86,77.17 ; J18.13 90.13,76.44 ; J18.13 89.4,77.17 ; J18.20 87.06,78.47 ; J18.20 85.28,76.69 ; J18.20 88.84,76.69 ; J18.20 87.06,74.91 ; J20.4 110.15,75.49 ; J20.4 109.15,76.49 ; J20.4 109.15,74.49 ; J20.4 108.15,75.49 ; SS1.1 21.16,22.62 ; SS1.1 18.38,25.4 ; SS1.1 18.38,19.84 ; SS1.1 15.6,22.62 ; 2.51,36.97 J3.4 ; J3.4 1.78,37.69 ; J3.4 3.24,37.69 ; J3.4 2.51,38.42 ; 71.6,59.62 SS4.1 ; SS4.1 74.38,62.4 ; SS4.1 74.38,56.84 ; SS4.1 77.16,59.62 ; 18.13,74.07 J10.2 ; J10.2 18.13,75.33 ; J10.2 18.75,74.7 ; J20.6 121.03,75.49 ; J20.6 117.37,75.49 ; J20.6 119.2,77.32 ; J20.6 119.2,73.66 ; J33.4 94,11.38 ; J33.4 94.73,10.65 ; J33.4 93.27,10.65 ; J33.4 94,9.93 ; J11.5 17.36,16.12 ; J11.5 15.21,16.12 ; J11.5 16.28,15.04 ; J11.5 16.28,17.2 ; J20.5 107.93,75.49 ; J20.5 104.27,75.49 ; J20.5 106.1,73.66 ; J20.5 106.1,77.32 ; 15.6,59.62 SS3.1 ; SS3.1 18.38,56.84 ; SS3.1 18.38,62.4 ; SS3.1 21.16,59.62 ; J9.4 3.05,28.37 ; J9.4 3.05,26.57 ; J9.4 2.15,27.47 ; J9.4 3.95,27.47 ; 83.4,17.52 J8.1 ; J8.1 84.33,18.45 ; J8.1 84.33,16.6 ; J8.1 85.26,17.52 ; J18.19 87.06,84.15 ; J18.19 85.28,82.37 ; J18.19 87.06,80.59 ; J18.19 88.84,82.37 ; U25.2 62.42,80.88 ; U25.2 61.84,81.46 ; U25.2 61.26,80.88 ; 104.27,81.29 J20.11 ; J20.11 106.1,79.46 ; J20.11 106.1,83.12 ; J20.11 107.93,81.29 ; 109.15,77.49 J20.10 ; J20.10 108.15,78.49 ; J20.10 110.15,78.49 ; J20.10 109.15,79.49 ; 92.9,75.67 J18.16 ; J18.16 93.63,74.94 ; J18.16 93.63,76.4 ; J18.16 94.36,75.67 ; 60.26,75.68 U25.11 61.42,75.68 ; 71.6,22.62 SS2.1 ; SS2.1 74.38,19.84 ; SS2.1 77.16,22.62 ; SS2.1 74.38,25.4 ; 69.27,10.65 J26.6 ; J26.6 70.73,10.65 ; J26.6 70,11.38 ; J26.6 70,9.93 ; J1.5 19.35,89.29 ; J1.5 18.67,87.92 ; J1.5 19.35,86.54 ; J1.5 20.03,87.92 ; J3.2 3.24,41.69 ; J3.2 1.78,41.69 ; J3.2 2.51,42.42 ; J3.2 2.51,40.97 ; J1.3 19.23,80.66 ; J1.3 18.5,79.19 ; J1.3 17.77,80.66 ; J1.3 18.5,82.14 ; 100.2,74.91 J18.21 ; J18.21 100.2,78.47 ; J18.21 101.98,76.69 ; J18.21 98.42,76.69 ; 9.55,86.54 J1.1 ; J1.1 10.23,87.92 ; J1.1 8.87,87.92 ; J1.1 9.55,89.29 ; 62.42,77.42 U25.8 61.26,77.42 ; 61.42,79.14 U25.5 60.26,79.14 ; J18.4 90.86,80.37 ; J18.4 90.13,81.1 ; J18.4 89.4,80.37 ; J18.4 90.13,79.64 ; J1.2 13.2,82.14 ; J1.2 13.2,79.19 ; J1.2 13.93,80.66 ; J1.2 12.47,80.66 ; SS5.1 92.1,21.9 ; SS5.1 89.32,19.12 ; SS5.1 94.88,19.12 ; SS5.1 92.1,16.34 ; J35.4 118,11.38 ; J35.4 118.73,10.65 ; J35.4 117.27,10.65 ; J35.4 118,9.93 ; 98.42,82.37 J18.22 ; J18.22 101.98,82.37 ; J18.22 100.2,84.15 ; J18.22 100.2,80.59 ; 1.78,33.69 J3.6 ; J3.6 2.51,32.97 ; J3.6 2.51,34.42 ; J3.6 3.24,33.69 ; 92.9,78.87 J18.7 ; J18.7 93.63,79.6 ; J18.7 94.36,78.87 ; J18.7 93.63,78.14 ; J11.2 27.71,17.2 ; J11.2 27.71,15.04 ; J11.2 28.79,16.12 ; J11.2 26.64,16.12 ; 61.42,72.21 U25.17 60.26,72.21
  GND02 w0.508: J17.15 84.9,78.04 ; J17.16 66.63,78.04
  ART03 w0.254: v1(75.18,87.12) 67.44,87.12 66.52,86.2 66.52,72.67 v1(67.18,72.01)
  ART03 w0.305: v1(75.18,87.12) v1(76.2,87.12) 87,87.12 87.5,86.61 87.5,85.22 88.77,83.95 110.23,83.95 v1(111.62,85.34) 110.67,86.29 108.26,86.29 106.81,84.83 89.65,84.83 88.77,85.71 88.77,86.99 87.63,88.14 67.18,88.14 65.53,86.49 65.53,71.85 65.94,71.45 66.62,71.45 v1(67.18,72.01)
  ART03 w0.686: 18.67,87.92 J1.5 ; J1.5 20.03,87.92 ; J1.5 19.35,86.54 ; J17.15 84.9,78.04 ; 92.9,78.87 J18.7 ; J18.7 93.63,78.14 ; J18.7 94.36,78.87 ; J18.7 93.63,79.6 ; 98.42,76.69 J18.21 ; J18.21 100.2,74.91 ; J18.21 101.98,76.69 ; J18.21 100.2,78.47 ; J35.4 118,11.38 ; J35.4 118.73,10.65 ; J35.4 117.27,10.65 ; J35.4 118,9.93 ; J18.4 90.86,80.37 ; J18.4 90.13,79.64 ; J18.4 90.13,81.1 ; J18.4 89.4,80.37 ; J33.4 94.73,10.65 ; J33.4 94,9.93 ; J33.4 94,11.38 ; J33.4 93.27,10.65 ; J18.13 90.86,77.17 ; J18.13 89.4,77.17 ; J18.13 90.13,76.44 ; J18.13 90.13,77.9 ; J26.6 70.73,10.65 ; J26.6 69.27,10.65 ; J26.6 70,11.38 ; J26.6 70,9.93 ; J3.2 3.24,41.69 ; J3.2 1.78,41.69 ; J3.2 2.51,42.42 ; J3.2 2.51,40.97 ; 2.15,27.47 J9.4 ; J9.4 3.05,28.37 ; J9.4 3.95,27.47 ; J9.4 3.05,26.57 ; 98.42,82.37 J18.22 ; J18.22 101.98,82.37 ; J18.22 100.2,80.59 ; 105.27,10.65 J34.4 ; J34.4 106.73,10.65 ; J34.4 106,11.38 ; J34.4 106,9.93 ; 85.28,76.69 J18.20 ; J18.20 87.06,74.91 ; J18.20 87.06,78.47 ; J18.20 88.84,76.69 ; J18.16 94.36,75.67 ; J18.16 93.63,76.4 ; J18.16 92.9,75.67 ; J18.16 93.63,74.94 ; J20.12 121.03,81.29 ; J20.12 119.2,83.12 ; J20.12 119.2,79.46 ; J20.12 117.37,81.29 ; J32.4 82,11.38 ; J32.4 82.73,10.65 ; J32.4 81.27,10.65 ; J32.4 82,9.93 ; J11.5 16.28,17.2 ; J11.5 17.36,16.12 ; J11.5 15.21,16.12 ; J11.5 16.28,15.04 ; 1.78,33.69 J3.6 ; J3.6 3.24,33.69 ; J3.6 2.51,32.97 ; J3.6 2.51,34.42 ; J11.2 27.71,17.2 ; J11.2 27.71,15.04 ; J11.2 26.64,16.12 ; J11.2 28.79,16.12 ; J20.10 109.15,79.49 ; J20.10 108.15,78.49 ; J20.10 109.15,77.49 ; J20.10 110.15,78.49 ; 9.55,86.54 J1.1 ; J1.1 8.87,87.92 ; J1.1 10.23,87.92 ; J20.5 106.1,77.32 ; J1.2 13.2,82.14 ; J1.2 13.2,79.19 ; J1.2 12.47,80.66 ; 1.78,37.69 J3.4 ; J3.4 2.51,38.42 ; J3.4 2.51,36.97 ; J3.4 3.24,37.69 ; 106.1,79.46 J20.11 ; J20.11 106.1,83.12 ; J20.11 107.93,81.29 ; J20.11 104.27,81.29 ; 87.06,80.59 J18.19 ; J18.19 85.28,82.37 ; J18.19 88.84,82.37 ; J18.19 87.06,84.15
  POW04 w0.686: J20.12 119.2,83.12 ; J20.12 119.2,79.46 ; J20.12 117.37,81.29 ; J20.12 121.03,81.29 ; 2.51,32.97 J3.6 ; J3.6 1.78,33.69 ; J3.6 2.51,34.42 ; J3.6 3.24,33.69 ; J18.7 94.36,78.87 ; J18.7 93.63,78.14 ; J18.7 92.9,78.87 ; J18.7 93.63,79.6 ; J1.3 19.23,80.66 ; J1.3 18.5,79.19 ; J1.3 17.77,80.66 ; J1.3 18.5,82.14 ; J18.4 90.13,81.1 ; J18.4 90.86,80.37 ; J18.4 89.4,80.37 ; J18.4 90.13,79.64 ; J3.2 3.24,41.69 ; J3.2 1.78,41.69 ; J3.2 2.51,40.97 ; J3.2 2.51,42.42 ; 87.06,80.59 J18.19 ; J18.19 88.84,82.37 ; J18.19 87.06,84.15 ; J18.19 85.28,82.37 ; 89.32,19.12 SS5.1 ; SS5.1 94.88,19.12 ; SS5.1 92.1,21.9 ; 85.26,17.52 J8.1 83.4,17.52 ; 70,9.93 J26.6 ; J26.6 69.27,10.65 ; J26.6 70.73,10.65 ; 117.37,75.49 J20.6 ; J20.6 121.03,75.49 ; J20.6 119.2,77.32 ; J20.6 119.2,73.66 ; J18.16 93.63,76.4 ; J18.16 93.63,74.94 ; J18.16 94.36,75.67 ; J18.16 92.9,75.67 ; 19.35,86.54 J1.5 ; J1.5 20.03,87.92 ; J1.5 18.67,87.92 ; J20.4 109.15,76.49 ; J20.4 109.15,74.49 ; J20.4 110.15,75.49 ; J20.4 108.15,75.49 ; 13.2,79.19 J1.2 ; J1.2 13.2,82.14 ; J1.2 13.93,80.66 ; J1.2 12.47,80.66 ; 60.26,75.68 U25.11 ; 22.62,74.34 J2.2 ; J2.2 22.62,75.74 ; J2.2 21.92,75.04 ; J20.11 107.93,81.29 ; J20.11 104.27,81.29 ; J20.11 106.1,83.12 ; J20.11 106.1,79.46 ; 90.13,76.44 J18.13 ; J18.13 90.13,77.9 ; J18.13 89.4,77.17 ; J18.13 90.86,77.17 ; J20.10 109.15,79.49 ; J20.10 108.15,78.49 ; J20.10 109.15,77.49 ; J20.10 110.15,78.49 ; 104.27,75.49 J20.5 ; J20.5 106.1,73.66 ; J20.5 107.93,75.49 ; J20.5 106.1,77.32 ; 2.51,36.97 J3.4 ; J3.4 3.24,37.69 ; J3.4 2.51,38.42 ; J3.4 1.78,37.69 ; J18.21 101.98,76.69 ; J18.21 98.42,76.69 ; J18.21 100.2,74.91 ; J18.21 100.2,78.47 ; 66.63,78.04 J17.16 ; J17.15 84.9,78.04 ; 98.42,82.37 J18.22 ; J18.22 100.2,84.15 ; J18.22 100.2,80.59 ; J18.22 101.98,82.37 ; J9.4 3.05,28.37 ; J9.4 3.05,26.57 ; J9.4 2.15,27.47 ; J9.4 3.95,27.47 ; 8.87,87.92 J1.1 ; J1.1 10.23,87.92 ; J1.1 9.55,86.54 ; U25.8 62.42,77.42 ; SS2.1 74.38,25.4 ; SS2.1 77.16,22.62 ; SS2.1 71.6,22.62 ; J10.2 18.75,74.7 ; J10.2 18.13,74.07 ; J10.2 18.13,75.33 ; 62.42,80.88 U25.2 61.84,81.46 ; 60.26,72.21 U25.17 ; SS6.1 119.08,19.12 ; SS6.1 116.3,16.34 ; SS6.1 113.52,19.12 ; SS6.1 116.3,21.9 ; J18.20 87.06,78.47 ; J18.20 88.84,76.69 ; J18.20 85.28,76.69 ; J18.20 87.06,74.91 ; J11.2 27.71,17.2 ; 60.26,79.14 U25.5
  GND05 w0.381: 70,9.93 J26.6 ; J26.6 70.73,10.65 ; J26.6 70,11.38 ; J26.6 69.27,10.65 ; 1.78,37.69 J3.4 ; J3.4 2.51,36.97 ; J3.4 3.24,37.69 ; J3.4 2.51,38.42 ; 94,9.93 J33.4 ; J33.4 94,11.38 ; J33.4 94.73,10.65 ; J33.4 93.27,10.65 ; 74.38,56.84 SS4.1 ; SS4.1 77.16,59.62 ; SS4.1 74.38,62.4 ; SS4.1 71.6,59.62 ; J35.4 118.73,10.65 ; J35.4 117.27,10.65 ; J35.4 118,11.38 ; J35.4 118,9.93 ; SS3.1 18.38,62.4 ; SS3.1 18.38,56.84 ; SS3.1 15.6,59.62 ; SS3.1 21.16,59.62 ; 104.27,75.49 J20.5 ; J20.5 106.1,77.32 ; J20.5 106.1,73.66 ; J20.5 107.93,75.49 ; SS6.1 119.08,19.12 ; SS6.1 116.3,16.34 ; SS6.1 113.52,19.12 ; SS6.1 116.3,21.9 ; J1.5 20.03,87.92 ; J1.5 18.67,87.92 ; J1.5 19.35,89.29 ; J1.5 19.35,86.54 ; 98.42,76.69 J18.21 ; J18.21 101.98,76.69 ; J18.21 100.2,78.47 ; J18.21 100.2,74.91 ; J2.2 23.32,75.04 ; J2.2 22.62,75.74 ; J2.2 21.92,75.04 ; J2.2 22.62,74.34 ; J11.5 16.28,17.2 ; J11.5 15.21,16.12 ; J11.5 17.36,16.12 ; J11.5 16.28,15.04 ; 60.26,75.68 U25.11 61.42,75.68 ; 74.38,19.84 SS2.1 ; SS2.1 74.38,25.4 ; SS2.1 71.6,22.62 ; SS2.1 77.16,22.62 ; J20.12 119.2,83.12 ; J20.12 119.2,79.46 ; J20.12 117.37,81.29 ; J20.12 121.03,81.29 ; J34.4 106.73,10.65 ; J34.4 106,9.93 ; J34.4 105.27,10.65 ; J34.4 106,11.38 ; 1.78,41.69 J3.2 ; J3.2 3.24,41.69 ; J3.2 2.51,40.97 ; J3.2 2.51,42.42 ; 98.42,82.37 J18.22 ; J18.22 101.98,82.37 ; J18.22 100.2,84.15 ; J18.22 100.2,80.59 ; 90.13,76.44 J18.13 ; J18.13 90.86,77.17 ; J18.13 89.4,77.17 ; J18.13 90.13,77.9 ; 61.26,80.88 U25.2 ; U25.2 62.42,80.88 ; U25.2 61.84,81.46 ; J1.2 13.2,82.14 ; J1.2 13.2,79.19 ; J1.2 13.93,80.66 ; J1.2 12.47,80.66 ; 66.63,78.04 J17.16 ; 83.4,17.52 J8.1 ; J8.1 84.33,18.45 ; J8.1 85.26,17.52 ; J8.1 84.33,16.6 ; 81.27,10.65 J32.4 ; J32.4 82.73,10.65 ; J32.4 82,11.38 ; J32.4 82,9.93 ; 109.15,77.49 J20.10 ; J20.10 108.15,78.49 ; J20.10 109.15,79.49 ; J20.10 110.15,78.49 ; J10.2 18.75,74.7 ; J10.2 18.13,74.07 ; J10.2 18.13,75.33 ; 90.13,79.64 J18.4 ; J18.4 89.4,80.37 ; J18.4 90.13,81.1 ; J18.4 90.86,80.37 ; J20.6 119.2,77.32 ; J20.6 121.03,75.49 ; J20.6 119.2,73.66 ; J20.6 117.37,75.49 ; 17.77,80.66 J1.3 ; J1.3 18.5,82.14 ; J1.3 19.23,80.66 ; J1.3 18.5,79.19 ; 109.15,74.49 J20.4 ; J20.4 109.15,76.49 ; J20.4 110.15,75.49 ; J20.4 108.15,75.49 ; 104.27,81.29 J20.11 ; J20.11 106.1,83.12 ; J20.11 107.93,81.29 ; J20.11 106.1,79.46 ; 93.63,74.94 J18.16 ; J18.16 94.36,75.67 ; J18.16 93.63,76.4 ; J18.16 92.9,75.67 ; SS5.1 92.1,21.9 ; SS5.1 92.1,16.34 ; SS5.1 94.88,19.12 ; SS5.1 89.32,19.12 ; SS1.1 18.38,25.4 ; SS1.1 18.38,19.84 ; SS1.1 15.6,22.62 ; SS1.1 21.16,22.62 ; 8.87,87.92 J1.1 ; J1.1 10.23,87.92 ; J1.1 9.55,89.29 ; J1.1 9.55,86.54 ; 61.42,72.21 U25.17 60.26,72.21 ; 85.28,76.69 J18.20 ; J18.20 87.06,74.91 ; J18.20 87.06,78.47 ; J18.20 88.84,76.69 ; J9.4 3.05,28.37 ; J9.4 3.95,27.47 ; J9.4 3.05,26.57 ; J9.4 2.15,27.47 ; 93.63,78.14 J18.7 ; J18.7 94.36,78.87 ; J18.7 93.63,79.6 ; J18.7 92.9,78.87 ; J17.15 84.9,78.04 ; 27.71,15.04 J11.2 ; J11.2 28.79,16.12 ; J11.2 26.64,16.12 ; J11.2 27.71,17.2 ; 61.42,79.14 U25.5 60.26,79.14 ; 62.42,77.42 U25.8 61.26,77.42 ; J18.19 88.84,82.37 ; J18.19 85.28,82.37 ; J18.19 87.06,84.15 ; J18.19 87.06,80.59 ; J3.6 2.51,34.42 ; J3.6 3.24,33.69 ; J3.6 1.78,33.69 ; J3.6 2.51,32.97
  BOTTOM w0.152: v1(63.12,48.39) 63.63,47.88 v1(68.33,47.88) 78.11,47.88 79.5,46.48 87.63,46.48 92.58,51.43 92.58,53.97 93.95,55.34 95.01,55.34 95.61,55.93 95.61,56.33 95.3,56.64 94.74,56.64 v1(94.23,56.13) 93.6,56.13 91.57,54.1 v1(91.57,51.81) 87.25,47.5 80.01,47.5 78.23,49.27 v1(77.09,49.27)
  BOTTOM w0.156: v1(63.12,48.39) 63.69,48.96 76.77,48.96 v1(77.09,49.27)
  BOTTOM w0.254: C84.2 65.9,60.84 v1(66.63,60.11) ; C64.2 v1(122.81,13.46) ; v1(0.76,70.1) R22.2 ; C37.1 5.74,68.08 v1(6.1,68.43) 6.45,68.08 R25.2 ; v1(128.78,51.94) 129.23,52.39 J24.4 ; v1(7.37,27.18) D6.1 4.11,26.41 J9.4 ; R75.2 v1(53.47,45.08) ; R6.2 v1(0.76,58.16) ; D31.1 v1(28.44,80.26) ; v1(1.99,55.88) 2.26,56.14 R8.2 C18.1 ; v1(77.6,17.4) D49.1 D50.1 v1(76.58,17.4) ; C74.2 v1(41.27,39.61) ; U14.5 54.11,39.61 v1(54.1,39.62) ; J23.18 128.94,76.16 v1(128.91,76.12) ; v1(18.67,41.65) R2.2 ; v1(12.19,24.73) C59.2 ; C87.2 87.11,59.19 R116.2 ; v1(117.93,40.13) 118.27,40.13 118.62,40.48 U37.2 ; v1(10.29,37.84) U7.2 v1(10.29,35.81) 12.31,35.81 C44.2 12.7,35.56 13.71,36.57 R33.2 v1(14.47,36.7) ; J12.12 v1(134.18,16.76) ; R78.2 v1(41.4,36.07) ; U9.3 v1(9.64,19.81) ; C6.2 v1(19.57,35.94) ; R29.2 v1(16.76,41.65) 16.76,42.24 Q6.2 ; D34.1 v1(68.07,67.18) ; v1(45.72,39.62) 45.73,39.61 U15.5 ; J12.13 122.99,18.97 v1(123.06,19.04) ; J23.4 v1(131.57,69.16) ; C9.2 v1(14.61,48.64) ; R203.2 107.11,50.67 v1(106.74,50.3) ; U10.3 v1(9.64,23.87) ; C73.2 v1(49.53,39.61) ; R77.2 v1(45.21,45.08) ; C57.2 v1(12.19,20.57) ; D30.1 v1(25.41,80.26) ; C53.2 R35.2 55.89,24.14 56.13,24.38 v1(56.13,26.1) ; C63.2 v1(123.83,13.46) ; v1(128.91,77.62) 128.94,77.66 J23.21 ; D5.1 v1(7.37,23.11) ; D35.1 54.61,67.7 v1(54.61,67.18) ; C173.2 35.04,69.76 v1(35.05,69.77) ; R5.2 v1(16.89,48.65) ; R76.2 v1(49.87,36.07) ; D36.1 v1(53.85,67.18)
  BOTTOM w0.305: v1(24.64,39.61) C67.2 C66.2 ; C68.2 v1(34.16,45.08) ; U13.15 v1(26.54,38.87)
  BOTTOM w0.381: C169.2 103.63,63.68 v1(102.8,64.51) ; v1(123.57,38.61) 123.19,38.99 U36.5 ; C42.2 v1(7.37,29.34) ; v1(88.65,61.47) 89.15,60.96 R121.1 ; v1(61.85,63.78) R154.2 D33.1 v1(60.83,63.78) ; C167.2 v1(99.18,67.57) ; C40.2 v1(5.97,38.35) ; D19.1 v1(117.22,30.22) ; v1(19.68,66.8) 20.28,66.8 20.54,67.05 U12.4 ; v1(107.7,69.85) U20.3 U20.8 v1(107.7,72.05) ; v1(31.75,69.77) D46.1 ; U2.2 v1(18.16,52.58) 18.8,51.94 C10.2 19.1,52.08 C11.2 v1(20.07,51.31) ; v1(36.45,69.77) R216.2 ; v1(53.72,76.83) U26.3 U26.8 v1(56.01,76.83) ; v1(63.88,63.78) D37.1 C129.2 v1(64.9,63.78) ; v1(75.39,65.15) 75.64,64.9 C92.2 ; v1(92.33,72.64) U18.8 U18.3 v1(92.33,69.85) ; v1(95.76,72.65) U19.8 U19.3 v1(95.76,69.85) ; C45.2 v1(7.37,33.91) ; D17.1 v1(117.22,26.29) ; C162.2 v1(114.64,42.54) ; v1(37.47,69.77) D43.1 ; D21.1 v1(117.22,32.51) ; v1(53.72,73.28) U27.3 U27.8 v1(56.01,73.28) ; v1(117.93,39.19) v1(117.93,40.13) ; 9.53,89.28 9.53,87.92 J1.1 ; C163.2 v1(114.64,43.56) ; C72.2 v1(117.22,27.68) ; C39.2 v1(7.37,38.35) ; v1(29.97,69.77) D45.1 ; C164.2 v1(114.64,39.5) ; v1(118.69,49.66) 118.82,49.53 R187.2 C143.2 ; C62.2 v1(124.84,9.52) ; C46.2 v1(5.97,33.91) ; R115.2 v1(76.2,87.12) ; D42.1 v1(35.05,69.77) ; D18.1 v1(117.22,29.08) ; D20.1 v1(117.22,31.37) ; U24.2 v1(25.27,68.71) ; v1(93.2,61.47) 92.46,62.21 C168.2 ; D15.1 v1(117.22,24) ; D16.1 v1(117.22,25.14) ; C43.2 v1(5.97,29.34) ; C89.2 79.24,65.9 79.63,66.29 v1(79.67,66.29) ; J1.5 19.35,89.3 ; R218.2 v1(54.86,83.06) ; C71.2 v1(114.55,27.68) ; R114.2 v1(75.18,87.12)
  BOTTOM w0.508: J34.4 107.68,10.65 108.17,11.14 C75.2 ; J12.6 121.5,27.76 v1(120.9,28.36) ; R150.2 v1(22.23,79)
  BOTTOM w0.635: 16.28,15.04 J11.5 ; J11.5 17.36,16.12 ; J11.5 15.21,16.12 ; 123.94,46.33 U36.8 125.17,47.01 ; 89.32,19.12 SS5.1 ; SS5.1 92.1,21.9 ; SS5.1 94.88,19.12 ; SS5.1 92.1,16.34 ; J1.3 19.23,80.66 ; J1.3 18.5,79.19 ; J1.3 17.77,80.66 ; J1.3 18.5,82.14 ; J34.4 106,11.38 ; J34.4 105.27,10.65 ; J34.4 106,9.93 ; 119.2,79.46 J20.12 ; J20.12 121.03,81.29 ; J20.12 117.37,81.29 ; J20.12 119.2,83.12 ; 123.94,33.33 U36.9 ; U36.9 122.71,34.01 ; U36.9 125.17,34.01 ; U36.9 123.94,34.69 ; J23.26 134.32,65.96 ; J23.26 133.14,66.93 ; J23.26 131.96,65.96 ; J3.6 3.24,33.69 ; J3.6 2.51,32.97 ; J3.6 2.51,34.42 ; J3.6 1.78,33.69 ; 18.67,87.92 J1.5 ; J1.5 19.35,86.54 ; J1.5 20.03,87.92 ; 9.55,86.54 J1.1 10.23,87.92 ; 131.96,64.09 J24.25 ; J24.25 134.32,64.09 ; J24.25 133.14,63.11 ; J26.6 70.73,10.65 ; J26.6 70,11.38 ; J26.6 69.27,10.65 ; J26.6 70,9.93 ; 93.27,10.65 J33.4 ; J33.4 94,11.38 ; J33.4 94.73,10.65 ; J33.4 94,9.93 ; 84.33,16.6 J8.1 ; J8.1 84.33,18.45 ; J8.1 85.26,17.52 ; J8.1 83.4,17.52 ; 131.96,80.86 J23.25 ; J23.25 133.14,79.88 ; J23.25 134.32,80.86 ; J23.25 133.14,81.83 ; J1.2 13.93,80.66 ; J1.2 13.2,82.14 ; J1.2 12.47,80.66 ; 134.71,47.01 U36.10 ; U36.10 135.94,47.69 ; U36.10 135.94,46.33 ; 132.59,31.32 J12.11 ; J12.11 133.97,32.26 ; J12.11 131.2,32.26 ; J12.11 132.59,33.2 ; J11.2 28.79,16.12 ; J11.2 26.64,16.12 ; J11.2 27.71,15.04 ; 74.38,19.84 SS2.1 77.16,22.62 ; 82,9.93 J32.4 ; J32.4 82,11.38 ; J32.4 82.73,10.65 ; J32.4 81.27,10.65 ; U36.11 135.94,34.69 ; U36.11 135.94,33.33 ; U36.11 134.71,34.01 ; 116.3,16.34 SS6.1 ; SS6.1 116.3,21.9 ; SS6.1 113.52,19.12 ; SS6.1 119.08,19.12 ; J35.4 118,11.38 ; J35.4 117.27,10.65 ; J35.4 118.73,10.65 ; J35.4 118,9.93 ; 122.99,33.04 J12.10 124.06,32.26 ; J24.26 133.14,50.17 ; J24.26 133.14,48.21 ; J24.26 134.32,49.19 ; 22.62,75.74 J2.2 22.62,74.34 ; 2.15,27.47 J9.4 ; J9.4 3.95,27.47 ; J9.4 3.05,26.57 ; J9.4 3.05,28.37
  vias: v1(0.76,86.95) v1(0.76,83.14) v1(0.76,79.37) v1(0.76,75.52) v1(0.76,67.9) v1(0.76,64.09) v1(0.76,60.28) v1(0.76,56.47) v1(0.76,52.66) v1(0.76,48.85) v1(0.76,45.04) v1(0.76,41.23) v1(0.76,37.42) v1(0.76,33.61) v1(0.76,29.8) v1(0.76,25.99) v1(0.76,22.18) v1(0.76,18.37) v1(0.76,14.56) v1(1.4,45.97) v1(4.03,16.38) v1(6.1,43.43) v1(6.91,89.24) v1(7.11,61.85) v1(7.11,60.83) v1(7.84,20.19) v1(7.84,16.38) v1(7.84,12.57) v1(7.84,8.76) v1(8.13,73.28) v1(8.13,61.85) v1(8.13,60.83) v1(8.38,69.34) v1(9.14,73.28) v1(9.4,69.34) v1(9.53,84.07) v1(9.53,50.42) v1(9.53,49.4) v1(10.16,74.29) v1(10.16,73.28) v1(10.29,33.27) v1(10.29,31.24) v1(10.54,50.42) v1(10.54,49.4) v1(10.72,89.24) v1(11.18,74.29) v1(11.18,73.28) v1(11.56,50.42) v1(11.56,49.4) v1(11.56,37.84) v1(11.65,12.57) v1(11.65,8.76) v1(12.45,84.07) v1(12.57,60.7) v1(12.57,59.69) v1(12.57,50.42) v1(12.57,49.4) v1(13.59,63.63) v1(13.59,62.61) v1(13.59,60.7) v1(13.59,59.69) v1(14.1,75.82) v1(14.39,32.13) v1(14.53,89.24) v1(14.61,63.63) v1(14.61,62.61) v1(15.11,75.82) v1(15.49,42.8) v1(15.46,12.57) v1(15.46,8.76) v1(16.64,87.76) v1(18.34,89.24) v1(18.54,29.59) v1(19.27,12.57) v1(19.27,8.76) v1(20.7,40.13) v1(22.15,89.24) v1(22.48,82.42) v1(22.61,40.89) v1(22.99,53.08) v1(23.08,12.57) v1(23.08,8.76) v1(23.24,35.3) v1(23.24,32) v1(23.45,82.42) v1(24.26,27.3) v1(24.64,73.28) v1(24.89,70.18) v1(25.27,29.64) v1(25.27,27.3) v1(25.5,19.02) v1(25.96,89.24) v1(26.29,27.3) v1(26.29,19.02) v1(26.89,12.57) v1(26.89,8.76) v1(27.05,85.85) v1(27.43,35.3) v1(27.43,32) v1(27.68,73.67) v1(28.21,65.41) v1(28.27,77.81) v1(29.46,86.87) v1(29.63,73.67) v1(29.63,59.05) v1(29.77,89.24) v1(30.1,29.46) v1(30.48,86.87) v1(30.48,76.83) v1(30.7,12.57) v1(30.7,8.76) v1(31.24,82.42) v1(32.26,82.42) v1(33.36,75.83) v1(33.36,73.67) v1(33.36,72.51) v1(33.58,89.24) v1(33.63,32) v1(34.42,55.12) v1(34.51,12.57) v1(34.51,8.76) v1(36.07,64.77) v1(36.2,81.28) v1(36.19,35.3) v1(36.19,32) v1(36.7,78.87) v1(37.39,89.24) v1(37.72,85.09) v1(38.18,72.77) v1(38.23,67.05) v1(38.32,8.76) v1(39.65,40.59) v1(40.28,10.53) v1(40.51,66.8) v1(41.15,32) v1(41.2,89.24) v1(41.91,85.09) v1(41.91,59.69) v1(42.04,79.88) v1(42.13,8.76) v1(42.42,32) v1(42.67,72.77) v1(42.67,70.48) v1(43.05,52.83) v1(43.81,74.55) v1(43.94,10.23) v1(44.7,75.94) v1(45.01,89.24) v1(45.47,32) v1(45.94,8.76) v1(46.61,32) v1(46.99,82.29) v1(46.99,78.48) v1(48.01,10.23) v1(48.13,25.14) v1(48.64,61.62) v1(48.82,89.24) v1(49.53,32) v1(49.75,8.76) v1(50.8,32) v1(51.59,11.78) v1(52.63,89.24) v1(52.83,81.02) v1(53.63,27.12) v1(53.56,8.76) v1(53.72,32) v1(54.86,79.25) v1(54.99,32) v1(55.63,35.94) v1(56.01,16.13) v1(56.44,89.24) v1(57.37,8.76) v1(58.03,31.37) v1(60.25,89.24) v1(60.58,52.45) v1(60.58,13.71) v1(60.71,31.37) v1(60.71,19.18) v1(61.18,8.76) v1(61.85,13.71) v1(63.42,31.37) v1(63.88,13.71) v1(64.06,89.24) v1(64.9,13.71) v1(64.99,8.76) v1(66.17,31.37) v1(67.06,85.85) v1(67.06,84.96) v1(67.61,60.11) v1(67.87,89.24) v1(68.65,59.13) v1(68.8,8.76) v1(70.61,23.11) v1(71.5,14.86) v1(71.68,89.24) v1(72.61,8.76) v1(74.18,40.58) v1(74.3,17.4) v1(75.49,89.24) v1(76.42,8.76) v1(77.09,14.81) v1(79.3,89.24) v1(80.23,8.76) v1(80.25,64.25) v1(81.03,66.93) v1(81.15,59.82) v1(82.04,60.7) v1(82.04,58.93) v1(82.93,61.59) v1(82.93,59.82) v1(82.93,58.04) v1(83.11,89.24) v1(83.07,54.91) v1(83.82,60.7) v1(83.82,58.93) v1(84.04,8.76) v1(84.45,86.99) v1(84.71,59.82) v1(86.92,89.24) v1(87.85,8.76) v1(88.9,72.64) v1(89.28,42.8) v1(89.31,39.83) v1(89.43,26.64) v1(89.79,57.66) v1(89.79,56.77) v1(89.79,54.86) v1(89.97,33.27) v1(90.73,89.24) v1(91.66,8.76) v1(92.1,42.8) v1(92.58,85.34) v1(93.34,33.4) v1(93.6,85.34) v1(94.54,89.24) v1(94.61,85.34) v1(94.79,50.05) v1(95,41.2) v1(95.47,8.76) v1(95.63,53.85) v1(95.63,50.04) v1(97.73,41.2) v1(98.35,89.24) v1(99.28,8.76) v1(101.85,19.43) v1(101.85,18.41) v1(101.85,17.4) v1(101.85,16) v1(102.16,89.24) v1(102.87,28.45) v1(102.87,27.43) v1(102.87,26.41) v1(102.87,25.4) v1(102.87,23.75) v1(102.87,22.73) v1(102.87,21.72) v1(102.87,20.45) v1(102.87,19.43) v1(102.87,16) v1(103,52.83) v1(103,51.31) v1(103.09,8.76) v1(103.25,30.35) v1(103.25,29.46) v1(103.89,28.95) v1(103.89,27.94) v1(103.89,26.92) v1(103.89,25.91) v1(103.89,24.89) v1(103.89,23.24) v1(103.89,22.22) v1(103.89,21.21) v1(103.89,16) v1(104.27,30.35) v1(104.52,52.83) v1(104.52,51.31) v1(104.9,16) v1(105.28,30.35) v1(105.66,26.92) v1(105.66,25.91) v1(105.66,24.89) v1(105.66,23.87) v1(105.66,22.86) v1(105.66,21.84) v1(105.66,20.83) v1(105.92,16) v1(105.97,89.24) v1(106.3,30.35) v1(106.3,28.32) v1(106.68,27.43) v1(106.68,26.41) v1(106.68,25.4) v1(106.68,24.38) v1(106.68,23.37) v1(106.68,22.35) v1(106.68,21.33) v1(106.68,20.32) v1(106.93,19.43) v1(106.93,16) v1(106.9,8.76) v1(107.31,30.35) v1(107.31,28.32) v1(107.7,27.43) v1(107.95,19.43) v1(107.95,18.41) v1(107.95,17.4) v1(107.95,16) v1(108.33,30.35) v1(108.33,28.32) v1(108.71,27.43) v1(109.35,30.35) v1(109.35,28.32) v1(109.78,89.24) v1(110.36,30.35) v1(110.36,28.32) v1(110.71,8.76) v1(111.38,30.35) v1(111.38,28.32) v1(112.01,29.46) v1(112.64,85.34) v1(113.28,82.68) v1(113.28,81.66) v1(113.59,89.24) v1(113.66,85.34) v1(114.05,52.83) v1(114.17,61.59) v1(114.17,60.58) v1(114.52,8.76) v1(114.94,36.07) v1(115.06,52.83) v1(115.95,36.07) v1(116.08,52.83) v1(117.4,89.24) v1(117.4,85.43) v1(117.91,43.94) v1(118.33,8.76) v1(118.99,22.2) v1(119.76,35.27) v1(120.4,72.13) v1(120.65,21.21) v1(121.21,89.24) v1(121.21,85.43) v1(121.79,63.8) v1(122.05,59.31) v1(122.14,8.76) v1(122.17,73.91) v1(122.17,34.29) v1(122.43,76.96) v1(122.81,63.8) v1(122.94,72.01) v1(123.19,59.31) v1(123.44,50.93) v1(123.57,45.59) v1(123.57,43.05) v1(124.17,27.05) v1(124.59,43.05) v1(124.59,38.61) v1(124.71,73.91) v1(125.02,89.24) v1(125.02,85.43) v1(125.02,81.62) v1(124.97,79.25) v1(125.18,27.05) v1(125.73,62.1) v1(125.73,57.85) v1(125.73,41.6) v1(125.73,37.03) v1(125.98,32.51) v1(125.95,8.76) v1(126.6,22.52) v1(126.6,19.83) v1(126.75,62.1) v1(126.75,57.85) v1(126.75,41.6) v1(126.75,37.03) v1(127,32.51) v1(127.64,53.47) v1(127.64,21.97) v1(128.83,89.24) v1(128.83,85.43) v1(128.83,81.62) v1(129.29,62.41) v1(129.76,8.76) v1(130.33,79.88) v1(131.06,29.72) v1(131.06,28.7) v1(131.57,67.56) v1(131.57,66.55) v1(132.59,33.55) v1(132.68,44) v1(132.68,41.27) v1(132.68,35.18) v1(132.68,19.18) v1(132.97,60.32) v1(133.14,50.59) v1(133.7,26.72) v1(133.7,22.91) v1(134.54,80.77) v1(134.47,47.01) v1(134.49,34.01) v1(134.65,64.09) v1(134.62,49.27) v1(134.75,73.28) v1(134.67,65.96) v1(135.13,70.1) v1(136.24,83.87) v1(136.24,80.06) v1(136.24,76.25) v1(136.24,72.44) v1(136.24,68.63) v1(136.24,64.82) v1(136.24,61.01) v1(136.24,57.2) v1(136.24,53.39) v1(136.24,49.58) v1(136.24,45.77) v1(136.24,41.96) v1(136.24,38.15) v1(136.24,30.53) v1(136.24,26.72) v1(136.24,22.91) v1(136.24,19.1) v1(136.24,15.29)
VCC3V3_SD: length 16.6
  TOP w0.254: v1(27.45,19.01) 27.63,19.19 J4.15 ; J4.17 28.13,19.23 v1(28.34,19.01)
  BOTTOM w0.381: J12.4 121.25,25.56 119.13,27.68 C72.1 118.99,27.6 118.38,26.99 117.02,26.99 C71.1 116.32,27.6 115.65,26.93 114.35,26.93 113.54,26.12 v1(113.54,24)
VCC3V3_SYS: length 46.4
  TOP w0.381: v1(124.33,61.59) 124.14,61.79 U30.5
  TOP w0.508: v1(18.69,43.33) 17.78,42.42 17.78,30.89 16.63,29.74 v1(10.29,29.74) ; v1(123.46,41.99) 124.08,41.99 U31.5
  POW04 w0.254: v1(22.61,41.78) 22.61,41.81
  BOTTOM w0.254: C16.1 10.03,66.67 9.68,67.03 3.28,67.03 2.44,66.19 2.44,60.34 R4.1 C8.1
  BOTTOM w0.508: v1(119.13,38.56) 118.34,37.77 115.8,37.77 115.05,37.02 U34.5 ; v1(22.61,41.78) 22.56,41.83 22.1,41.83 U1.5 ; U6.5 v1(10.29,29.74)
  vias: v1(13.59,65.66) v1(13.59,64.64) v1(14.61,65.66) v1(14.61,64.64)
VCC5V0_SYS: length 31
  TOP w0.254: R16.1 7.29,54.79 7.62,55.12 10.92,55.12 v1(11.56,55.75)
  TOP w0.381: U28.5 v1(124.14,56.89) ; U29.5 v1(124.14,36.37)
  BOTTOM w0.254: C20.1 R11.1 2.29,49.03 3.17,49.91 3.17,54.74 3.56,55.12 8.13,55.12 9.3,56.29 11.02,56.29 v1(11.56,55.75)
  BOTTOM w0.381: U33.5 122.05,51.51 v1(122.05,52.45)
  BOTTOM w0.508: U2.5 13.28,53.53 12.83,53.08 C26.1 ; v1(123.06,66.8) 121.92,66.8 121.43,66.31 U32.5
  vias: v1(11.56,54.74) v1(12.57,55.75) v1(12.57,54.74) v1(24.13,23.11) v1(24.13,22.1) v1(25.02,23.11) v1(25.02,22.1)
VCC5V0_SYS_2: length 76.2
  TOP w0.381: R10.1 v1(22.61,66.42)
  ART03 w0.762: v1(14.1,76.83) 14.07,76.83 13.36,76.12 13.36,74.19 11.05,71.88 5.84,71.88 4.83,70.86 4.83,50.29 8.51,46.61 v1(8.51,34.31)
  BOTTOM w0.254: C29.1 R20.1 2.17,73.73 3.3,74.87 3.3,78.61 3.56,78.87 13.72,78.87 14.1,78.48 v1(14.1,77.85)
  BOTTOM w0.381: U7.5 v1(8.51,34.31)
  BOTTOM w0.635: v1(22.61,66.42) 22.61,70.36
  vias: v1(15.11,77.85) v1(15.11,76.83) v1(55.43,88.22) v1(56.44,88.22)
VCC5V0_USB20_HOST: length 6.8
  BOTTOM w0.762: J20.1 J20.7 116.15,80.69 C111.1
VCC5V0_USB30_HOST: length 3.6
  TOP w0.508: J18.10 96.63,77.67 96.63,79.87 J18.1
VCC_1V8: length 29
  TOP w0.254: J4.13 27.13,21.92 v1(27.3,22.1) ; v1(26.42,22.1) 26.63,21.88 J4.11
  TOP w0.381: R37.1 R36.1 87.75,27.95 88.27,27.43 v1(88.27,25.53) C54.1 C55.1 85.61,25.53 84.96,24.89 U8.8 ; L7.2 93.14,51.04 C103.1 v1(94.79,51.04)
  BOTTOM w0.508: v1(95.63,51.05) 94.8,51.05 v1(94.79,51.04) 88.27,44.52 v1(88.27,39.83)
VCC_12V: length 21.3
  TOP w0.508: 10.79,61.59 14.86,61.59 16.64,63.37 21.93,63.37 R9.1
  BOTTOM w0.254: v1(10.41,68.32) 7.87,68.32 R23.1 ; R7.1 7.88,56.14 8.76,57.02 8.76,58.13 ; R14.1 8.44,44.2 8.51,44.27 8.89,44.27
  vias: v1(10.41,69.34) v1(11.43,69.34) v1(11.43,68.32) v1(12.57,58.67) v1(12.57,57.66) v1(12.57,46.73) v1(12.57,45.72) v1(12.95,42.16) v1(13.59,58.67) v1(13.59,57.66) v1(13.59,46.73) v1(13.59,45.72) v1(13.97,42.16) v1(14.61,46.73) v1(14.61,45.72) v1(115.06,49.66) v1(116.08,49.66) v1(117.09,49.66) v1(120.27,32.51) v1(121.16,32.51)
